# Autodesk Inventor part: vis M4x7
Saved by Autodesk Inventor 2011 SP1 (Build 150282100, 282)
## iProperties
Created: 2010-12
Part Number: vis M4x7
Document SubType Name: Modeling
Designer: eric
Density: 1 g/cm^3
Author: eric
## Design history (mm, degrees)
feature "Base1"
node "Solide1"
node "Corps solides"
node "Corps surfaciques"
